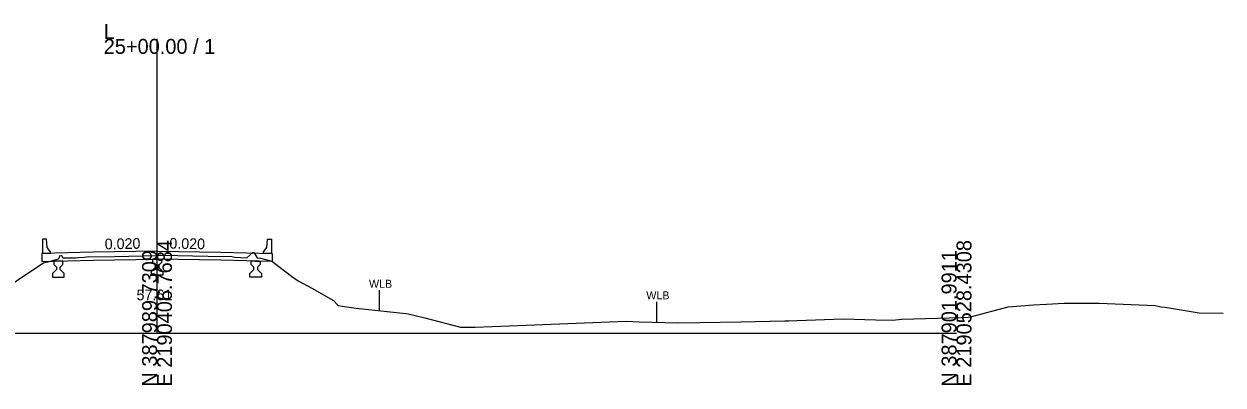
# Model space of a CAD drawing. Extents: x -26 to 2190750, y -10 to 388496.
# Drawn here: x 175 to 400, y 8990.3 to 9058 of the extents above; entities that cross this region are included whole.
import ezdxf

# ---------------------------------------------------------------- set-up
doc = ezdxf.new("R2010")
doc.units = 0
for name, color, linetype in [('Exist Cross Section Cell', 7, 'Continuous'), ('Exist XS Center Line Elevation Label', 7, 'Continuous'), ('Exist XS Ground Line', 7, 'Continuous'), ('Prop CMT Concrete Structures', 7, 'Continuous'), ('Prop RDY Alternate Text Blue', 7, 'Continuous'), ('Prop XS SE Text', 7, 'Continuous')]:
    doc.layers.add(name, color=color, linetype=linetype)

msp = doc.modelspace()

# ---------------------------------------------------------------- linework, layer by layer
at = {"layer": 'Exist Cross Section Cell'}
for p, q in [((200, 9000), (200, 9055.19)), ((50, 9000), (200, 9000)), ((200, 9000), (350, 9000))]:
    msp.add_line(p, q, dxfattribs=at)
at = {"layer": 'Exist XS Ground Line'}
msp.add_lwpolyline([(168.79, 9006.68), (178.36, 9013.02), (178.69, 9013.2), (179.74, 9013.46), (181.49, 9013.98), (181.89, 9014.64), (182.06, 9014.6), (182.32, 9014.12), (184.69, 9014.17), (185.25, 9014.21), (186.32, 9014.26), (187.22, 9014.42), (189.38, 9014.34), (200, 9014.61), (201.02, 9014.62), (212.42, 9014.38), (213.73, 9014.43), (214.61, 9014.27), (216.84, 9014.13), (218, 9015.12), (218.16, 9015.12), (218.76, 9014.14), (219.42, 9014.1), (221.54, 9013.5), (225.23, 9010.72), (226.46, 9009.82), (229.05, 9008.44), (233.14, 9006.13), (233.89, 9005.31), (234.05, 9005.24), (234.74, 9005.1), (237.38, 9004.7), (246.71, 9003.72), (247.15, 9003.68), (250.24, 9002.88), (256.94, 9001.12), (259.71, 9001.12), (269.28, 9001.53), (288.05, 9002.29), (290.43, 9002.15), (297.74, 9001.98), (301.84, 9002.03), (309.54, 9002.16), (317.78, 9002.36), (318.53, 9002.35), (320.04, 9002.41), (328.76, 9002.72), (334.89, 9002.54), (338.02, 9002.49), (339.71, 9002.67), (350.89, 9002.99), (352.16, 9003.04), (352.64, 9003.11), (359.69, 9004.98), (364.46, 9005.33), (366.86, 9005.45), (370.18, 9005.67), (376.79, 9005.62), (387.27, 9005.19), (388.34, 9004.98), (389.16, 9004.89), (395.53, 9003.86), (400, 9003.8)], dxfattribs=at)
at = {"layer": 'Prop CMT Concrete Structures'}
for points in [[(180, 9015.02), (180, 9015.27), (179.42, 9016.08), (179.25, 9017.66), (178.5, 9017.66), (178.5, 9014.99)], [(220, 9015.02), (220, 9015.27), (220.58, 9016.08), (220.75, 9017.66), (221.5, 9017.66), (221.5, 9014.99)], [(200, 9015.42), (188, 9015.18), (178.37, 9014.99)], [(178.37, 9014.99), (178.37, 9013.49)], [(178.5, 9014.99), (180, 9015.02)], [(200, 9013.92), (200, 9015.42)], [(200, 9015.42), (212, 9015.18), (221.62, 9014.99)], [(221.5, 9014.99), (220, 9015.02)], [(221.62, 9014.99), (221.62, 9013.49)], [(178.37, 9013.49), (188, 9013.68), (200, 9013.92)], [(181.17, 9011.97), (180.42, 9011.22)], [(182.33, 9013.57), (181.5, 9013.55), (180.67, 9013.54)], [(180.67, 9013.54), (180.67, 9012.89)], [(180.67, 9012.89), (181.17, 9012.39)], [(181.17, 9012.39), (181.17, 9011.97)], [(181.83, 9012.39), (182.33, 9012.89)], [(181.83, 9011.97), (181.83, 9012.39)], [(182.58, 9011.22), (181.83, 9011.97)], [(182.33, 9012.89), (182.33, 9013.57)], [(199.67, 9012.34), (198.92, 9011.59)], [(200, 9013.92), (199.17, 9013.91)], [(199.17, 9013.91), (199.17, 9013.26)], [(199.17, 9013.26), (199.67, 9012.76)], [(199.67, 9012.76), (199.67, 9012.34)], [(221.62, 9013.49), (212, 9013.68), (200, 9013.92)], [(200, 9013.92), (200.83, 9013.91)], [(200.83, 9013.26), (200.33, 9012.76)], [(200.33, 9012.76), (200.33, 9012.34)], [(200.33, 9012.34), (201.08, 9011.59)], [(200.83, 9013.91), (200.83, 9013.26)], [(217.42, 9011.22), (218.17, 9011.97)], [(217.67, 9013.57), (218.5, 9013.55), (219.33, 9013.54)], [(217.67, 9012.89), (217.67, 9013.57)], [(218.17, 9012.39), (217.67, 9012.89)], [(218.17, 9011.97), (218.17, 9012.39)], [(219.33, 9012.89), (218.83, 9012.39)], [(218.83, 9012.39), (218.83, 9011.97)], [(218.83, 9011.97), (219.58, 9011.22)], [(219.33, 9013.54), (219.33, 9012.89)], [(180.42, 9011.22), (180.42, 9010.55)], [(180.42, 9010.55), (181.5, 9010.55), (182.58, 9010.55)], [(182.58, 9010.55), (182.58, 9011.22)], [(198.92, 9011.59), (198.92, 9010.92)], [(198.92, 9010.92), (200, 9010.92)], [(201.08, 9010.92), (200, 9010.92)], [(201.08, 9011.59), (201.08, 9010.92)], [(217.42, 9010.55), (217.42, 9011.22)], [(219.58, 9010.55), (218.5, 9010.55), (217.42, 9010.55)], [(219.58, 9011.22), (219.58, 9010.55)]]:
    msp.add_lwpolyline(points, dxfattribs=at)
at = {"layer": 'Prop RDY Alternate Text Blue'}
for p, q in [((241.69, 9008.07), (241.69, 9004.25)), ((293.72, 9005.9), (293.72, 9002.08))]:
    msp.add_line(p, q, dxfattribs=at)

# ---------------------------------------------------------------- texts
at = {"layer": 'Exist Cross Section Cell'}
for s, p in [('L', (190, 9055.19)), ('25+00.00 / 1', (190, 9052.39))]:
    msp.add_text(s, height=2.8, dxfattribs=at).set_placement(p)
for s, p in [('E 2190406.7684', (202.8, 8990)), ('E 2190528.4308', (352.8, 8990)), ('N 387989.7309', (200, 8990)), ('N 387901.9911', (350, 8990))]:
    msp.add_text(s, height=2.8, rotation=90, dxfattribs=at).set_placement(p)
at = {"layer": 'Exist XS Center Line Elevation Label'}
msp.add_text('57.61', height=2, dxfattribs=at).set_placement((196.16, 9006.2))
at = {"layer": 'Prop RDY Alternate Text Blue'}
for p in [(239.77, 9008.54), (291.8, 9006.36)]:
    msp.add_text('WLB', height=1.5, dxfattribs=at).set_placement(p)
at = {"layer": 'Prop XS SE Text'}
for rotation, p in [(1.1458, (190.21, 9015.73)), (358.8542, (202.3, 9015.88))]:
    msp.add_text('0.020', height=2, rotation=rotation, dxfattribs=at).set_placement(p)

doc.saveas('drawing.dxf')
